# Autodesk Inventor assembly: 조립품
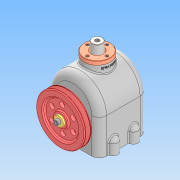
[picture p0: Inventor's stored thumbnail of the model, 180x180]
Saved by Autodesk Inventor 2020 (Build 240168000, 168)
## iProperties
Created: 2023-03
Part Number: 조립품
Document SubType Name: Assembly
Designer: user
Author: user
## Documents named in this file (22)
- C:\Users\user\Desktop\730306V1011\조립품.iam
- C:\Users\user\Desktop\730306V1011\본체.ipt
- C:\Users\user\Desktop\730306V1011\베어링 6205.ipt
- 베어링 6205.ipt
- C:\Users\user\Desktop\730306V1011\편심축.ipt
- C:\Users\user\Desktop\730306V1011\뒷커버.ipt
- C:\Users\user\Desktop\730306V1011\부시.ipt
- C:\Users\user\Desktop\730306V1011\슬라이더.ipt
- C:\Users\user\Desktop\730306V1011\E형 멈춤링 13 x 12.ipt
- C:\Users\user\Desktop\730306V1011\고정핀.ipt
- C:\Users\user\Desktop\730306V1011\링크.ipt
- C:\Users\user\Desktop\730306V1011\윗커버.ipt
- C:\Users\user\Desktop\730306V1011\멈춤링 25 x 1.2.ipt
- 멈춤링 25 x 1.2.ipt
- C:\Users\user\Desktop\730306V1011\앞커버.ipt
- C:\Users\user\Desktop\730306V1011\오일실 25 40 8.ipt
- 오일실 25 40 8.ipt
- C:\Users\user\Desktop\730306V1011\볼트 M4 x 12.ipt
- C:\Users\user\Desktop\730306V1011\V-벨트풀리.ipt
- C:\Users\user\Desktop\730306V1011\키 6x6x14.ipt
- C:\Users\user\Desktop\730306V1011\볼트 M8 x 16.ipt
- C:\Users\user\Desktop\730306V1011\엔드캡.ipt
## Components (3 placed, 3 different names)
1. E형 멈춤링 13 x 12:1
2. 고정핀:1
3. V-벨트풀리:1
